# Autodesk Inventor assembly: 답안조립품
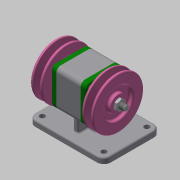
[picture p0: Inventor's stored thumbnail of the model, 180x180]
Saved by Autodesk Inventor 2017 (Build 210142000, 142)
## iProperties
Part Number: 답안조립품
Material: 일반
Document SubType Name: Assembly
Designer: mrc
Author: mrc
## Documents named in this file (10)
- C:\Users\mrc\Desktop\701106V1026\답안조립품.iam
- C:\Users\mrc\Desktop\701106V1026\너트 M10x1.ipt
- C:\Users\mrc\Desktop\701106V1026\베어링 6004.ipt
- C:\Users\mrc\Desktop\701106V1026\본체.ipt
- C:\Users\mrc\Desktop\701106V1026\V-벨트풀리.ipt
- C:\Users\mrc\Desktop\701106V1026\볼트 M4.ipt
- C:\Users\mrc\Desktop\701106V1026\오일 실 17 30 5.ipt
- C:\Users\mrc\Desktop\701106V1026\축.ipt
- C:\Users\mrc\Desktop\701106V1026\커버.ipt
- C:\Users\mrc\Desktop\701106V1026\키 5 x 5 x 12.ipt
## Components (2 placed, 1 different names)
1. V-벨트풀리:2
2. V-벨트풀리:3
